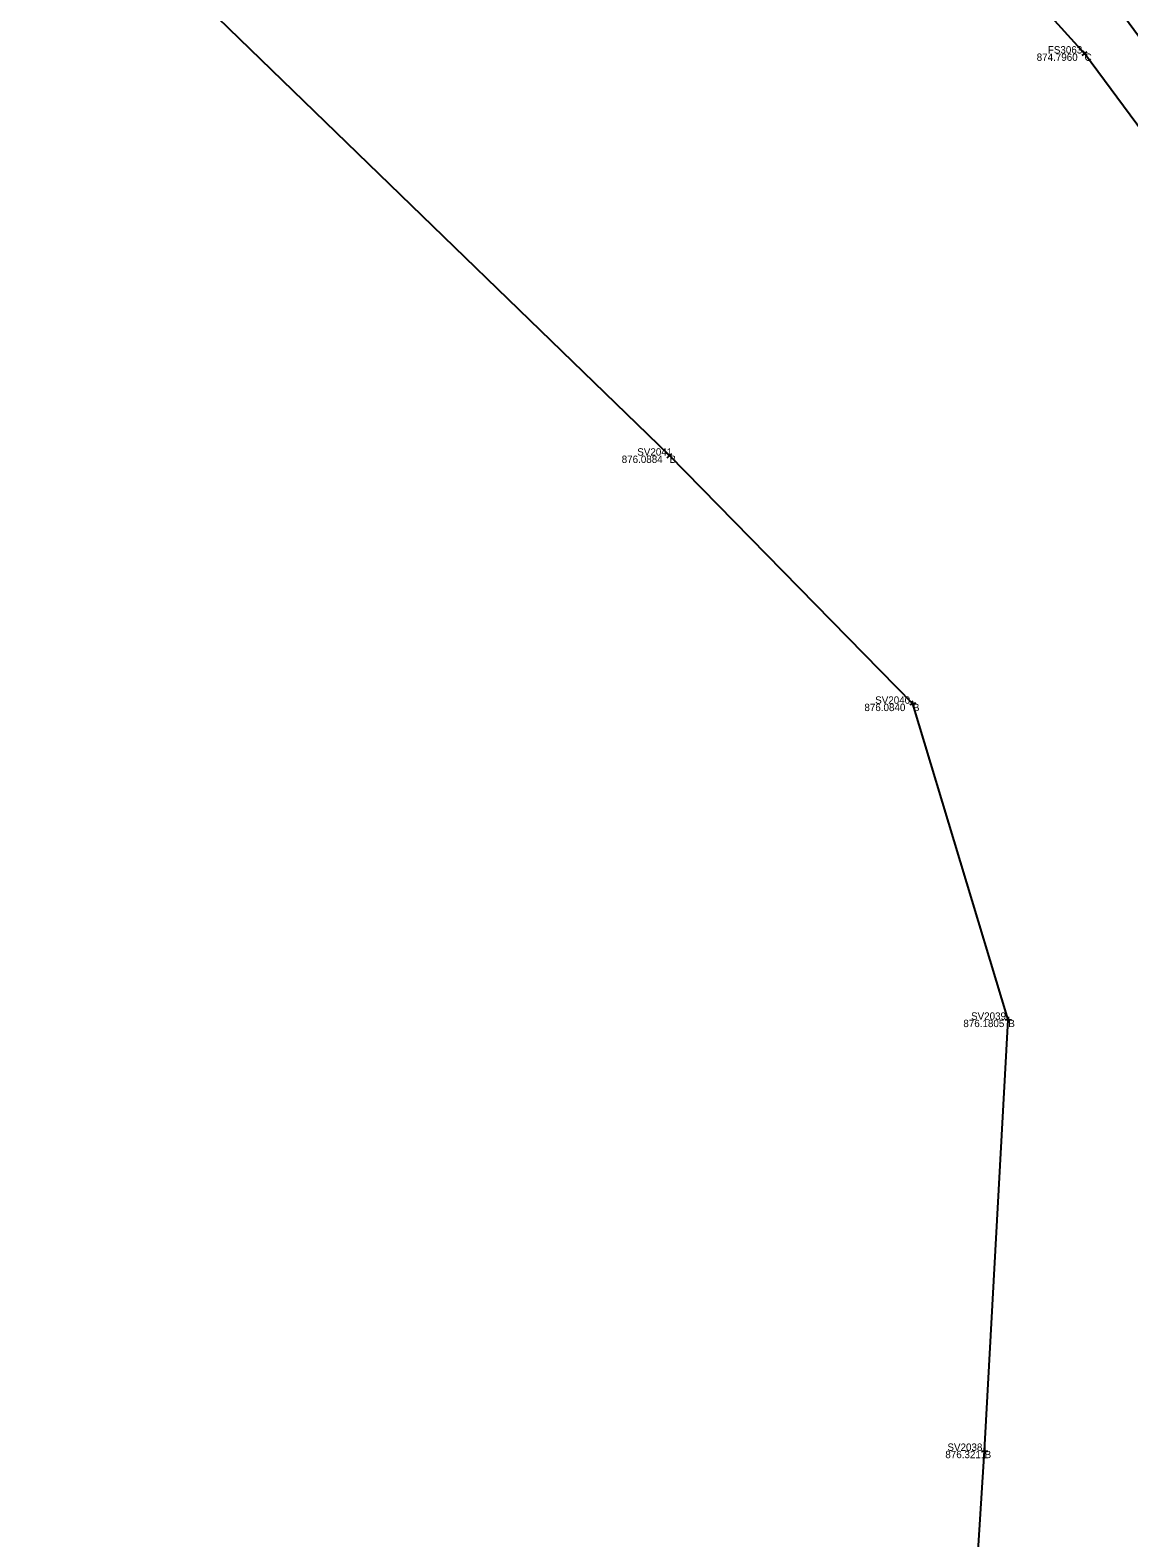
# Model space of a CAD drawing. Extents: x 1479481 to 1575806, y 316056 to 379927.
# Drawn here: x 1480127.81 to 1480136.78, y 379408.84 to 379421.16 of the extents above; entities that cross this region are included whole.
import ezdxf

# ---------------------------------------------------------------- set-up
doc = ezdxf.new("R2010")
doc.units = 0
for name, color, linetype in [('PV_X_Curb', 7, 'Continuous'), ('SV_X_Break_Lines', 7, 'Continuous'), ('SV_X_Shot_Marker', 7, 'Continuous'), ('SV_X_Text_Comment', 7, 'Continuous'), ('SV_X_Text_Elevation', 7, 'Continuous'), ('SV_X_Text_Name', 7, 'Continuous')]:
    doc.layers.add(name, color=color, linetype=linetype)

msp = doc.modelspace()

# ---------------------------------------------------------------- linework, layer by layer
at = {"layer": 'PV_X_Curb'}
msp.add_lwpolyline([(1480132.735, 379425.624), (1480133.489, 379424.793), (1480135.438, 379422.771), (1480136.612, 379421.448), (1480137.609, 379420.095), (1480138.484, 379418.724), (1480139.167, 379417.086), (1480139.644, 379414.697), (1480139.873, 379412.175), (1480139.928, 379410.1), (1480139.896, 379409.023), (1480139.487, 379409.126), (1480139.398, 379410.762), (1480139.445, 379412.342), (1480139.28, 379413.822), (1480139.072, 379415.451), (1480138.646, 379416.869), (1480138.065, 379418.417), (1480137.434, 379419.594), (1480136.416, 379420.968), (1480135.065, 379422.458), (1480133.739, 379423.908), (1480132.463, 379425.289)], dxfattribs=at)
at = {"layer": 'SV_X_Break_Lines'}
msp.add_lwpolyline([(1480127.721, 379395.358), (1480131.799, 379398.039), (1480133.273, 379401.352), (1480135.459, 379407.36), (1480135.6, 379409.555), (1480135.793, 379413.076), (1480135.014, 379415.657), (1480133.026, 379417.684), (1480123.803, 379426.624), (1480113.121, 379435.343), (1480106.984, 379440.926), (1480103.73, 379443.918), (1480102.529, 379445.074), (1480100.774, 379445.951), (1480096.595, 379444.059), (1480092.174, 379441.029), (1480086.377, 379436.591)], dxfattribs=at)
at = {"layer": 'SV_X_Shot_Marker'}
for p, q in [((1480136.396, 379420.953), (1480136.436, 379420.983)), ((1480136.431, 379420.948), (1480136.401, 379420.988)), ((1480136.416, 379420.968), (1480136.416, 379420.968)), ((1480133.044, 379417.666), (1480133.008, 379417.702)), ((1480133.008, 379417.666), (1480133.044, 379417.701)), ((1480133.026, 379417.684), (1480133.026, 379417.684)), ((1480134.99, 379415.65), (1480135.038, 379415.664)), ((1480135.021, 379415.633), (1480135.007, 379415.681)), ((1480135.014, 379415.657), (1480135.014, 379415.657)), ((1480135.768, 379413.077), (1480135.818, 379413.075)), ((1480135.792, 379413.051), (1480135.794, 379413.101)), ((1480135.793, 379413.076), (1480135.793, 379413.076)), ((1480135.598, 379409.53), (1480135.602, 379409.58)), ((1480135.575, 379409.556), (1480135.625, 379409.553)), ((1480135.6, 379409.555), (1480135.6, 379409.555))]:
    msp.add_line(p, q, dxfattribs=at)

# ---------------------------------------------------------------- texts
at = {"layer": 'SV_X_Text_Comment'}
for s, p in [('C', (1480136.416, 379420.908)), ('B', (1480133.026, 379417.624)), ('B', (1480135.014, 379415.597)), ('B', (1480135.793, 379413.016)), ('B', (1480135.6, 379409.495))]:
    msp.add_text(s, height=0.06, dxfattribs=at).set_placement(p)
at = {"layer": 'SV_X_Text_Elevation'}
for s, p in [('874.7960', (1480136.025, 379420.908)), ('876.0884', (1480132.636, 379417.624)), ('876.0840', (1480134.618, 379415.597)), ('876.1805', (1480135.426, 379413.016)), ('876.3211', (1480135.279, 379409.495))]:
    msp.add_text(s, height=0.06, dxfattribs=at).set_placement(p)
at = {"layer": 'SV_X_Text_Name'}
for s, p in [('FS3063', (1480136.116, 379420.968)), ('SV2041', (1480132.763, 379417.684)), ('SV2040', (1480134.706, 379415.657)), ('SV2039', (1480135.489, 379413.076)), ('SV2038', (1480135.296, 379409.555))]:
    msp.add_text(s, height=0.06, dxfattribs=at).set_placement(p)

doc.saveas('drawing.dxf')
